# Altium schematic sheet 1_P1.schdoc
size 601 x 429 mm; Symbol: Drawing-Symbol_A2; Device: Drawing-Symbol_A2; Company: 嘉立创EDA; Version: V1.0; Page Size: A2; @Project Name: OpenSource_FlyPig v1; @Page Count: 1; @Update Date: 2025-10-14; @Create Date: 2025-10-14; @Schematic Name: Schematic1; @Page No: 1; @Page Name: P1; @Create Time: 16:01:13; @Update Time: 16:07:16; Width: 2338; Height: 1652; Region Start: 1; X Region Count: 6; Y Region Count: 4; Blade Width: 10; Title Block Position: 3; @Board Name: Board1
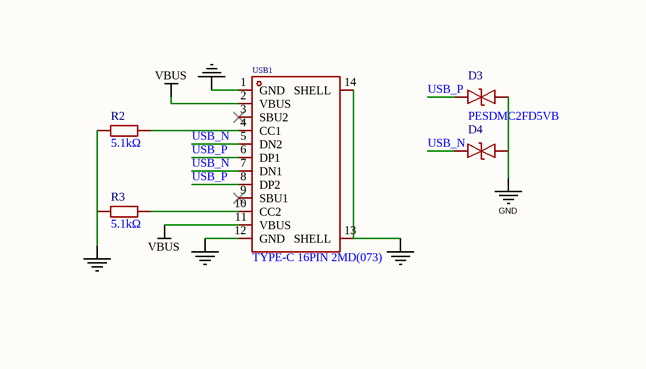
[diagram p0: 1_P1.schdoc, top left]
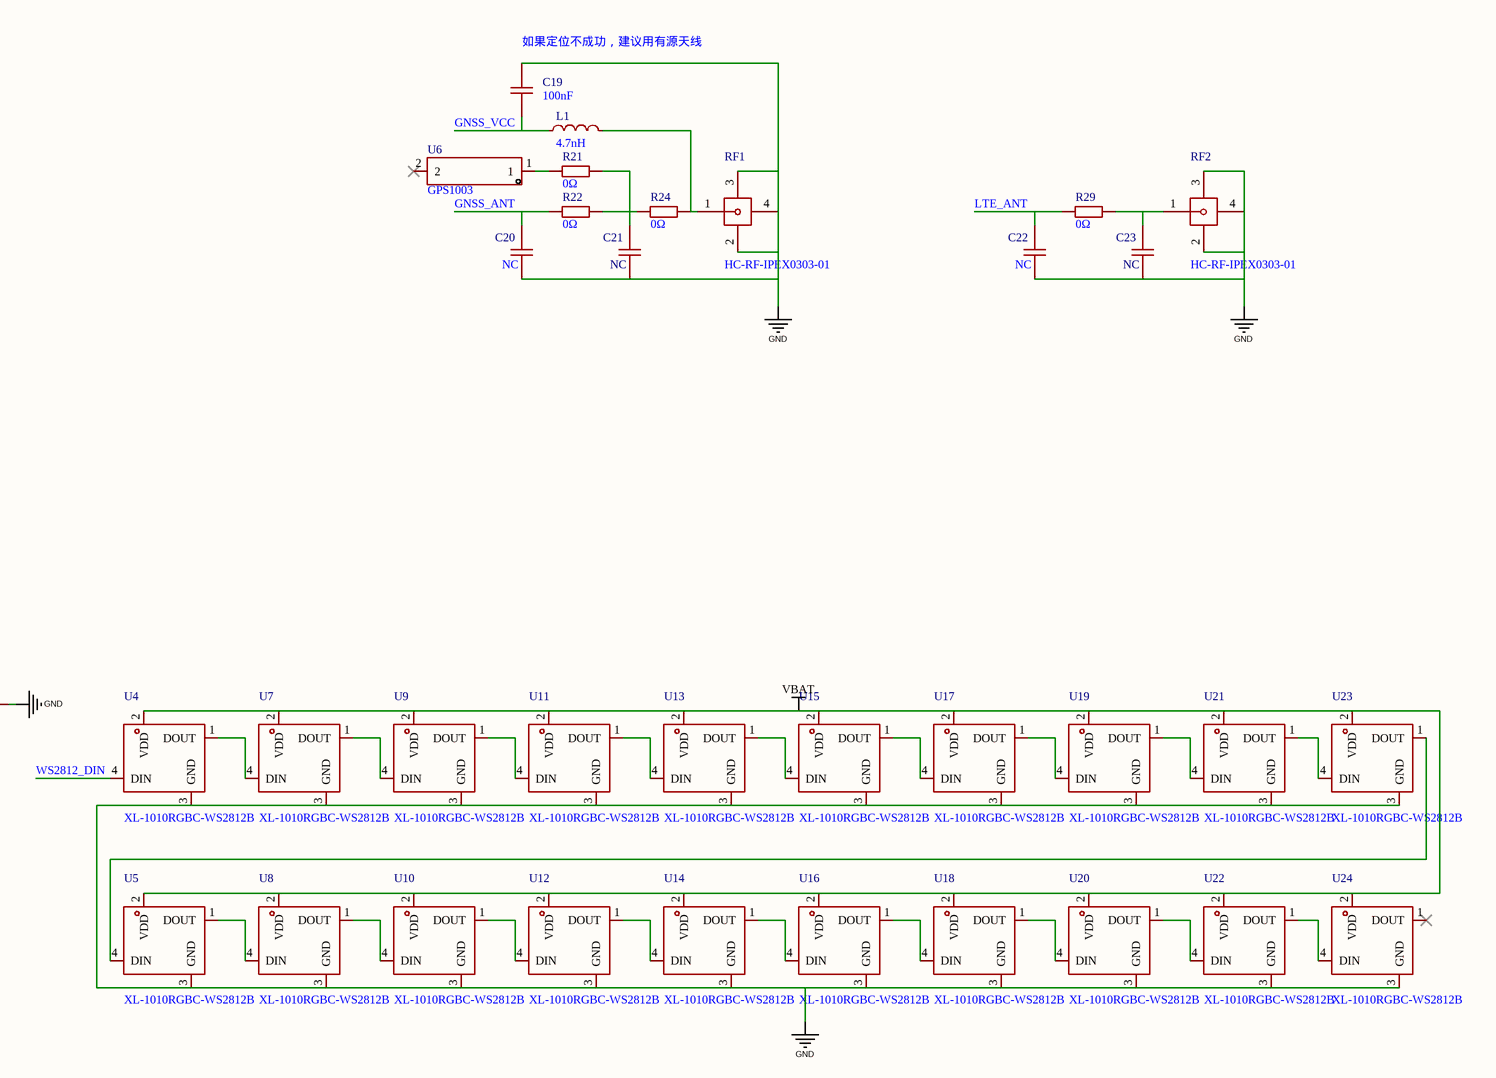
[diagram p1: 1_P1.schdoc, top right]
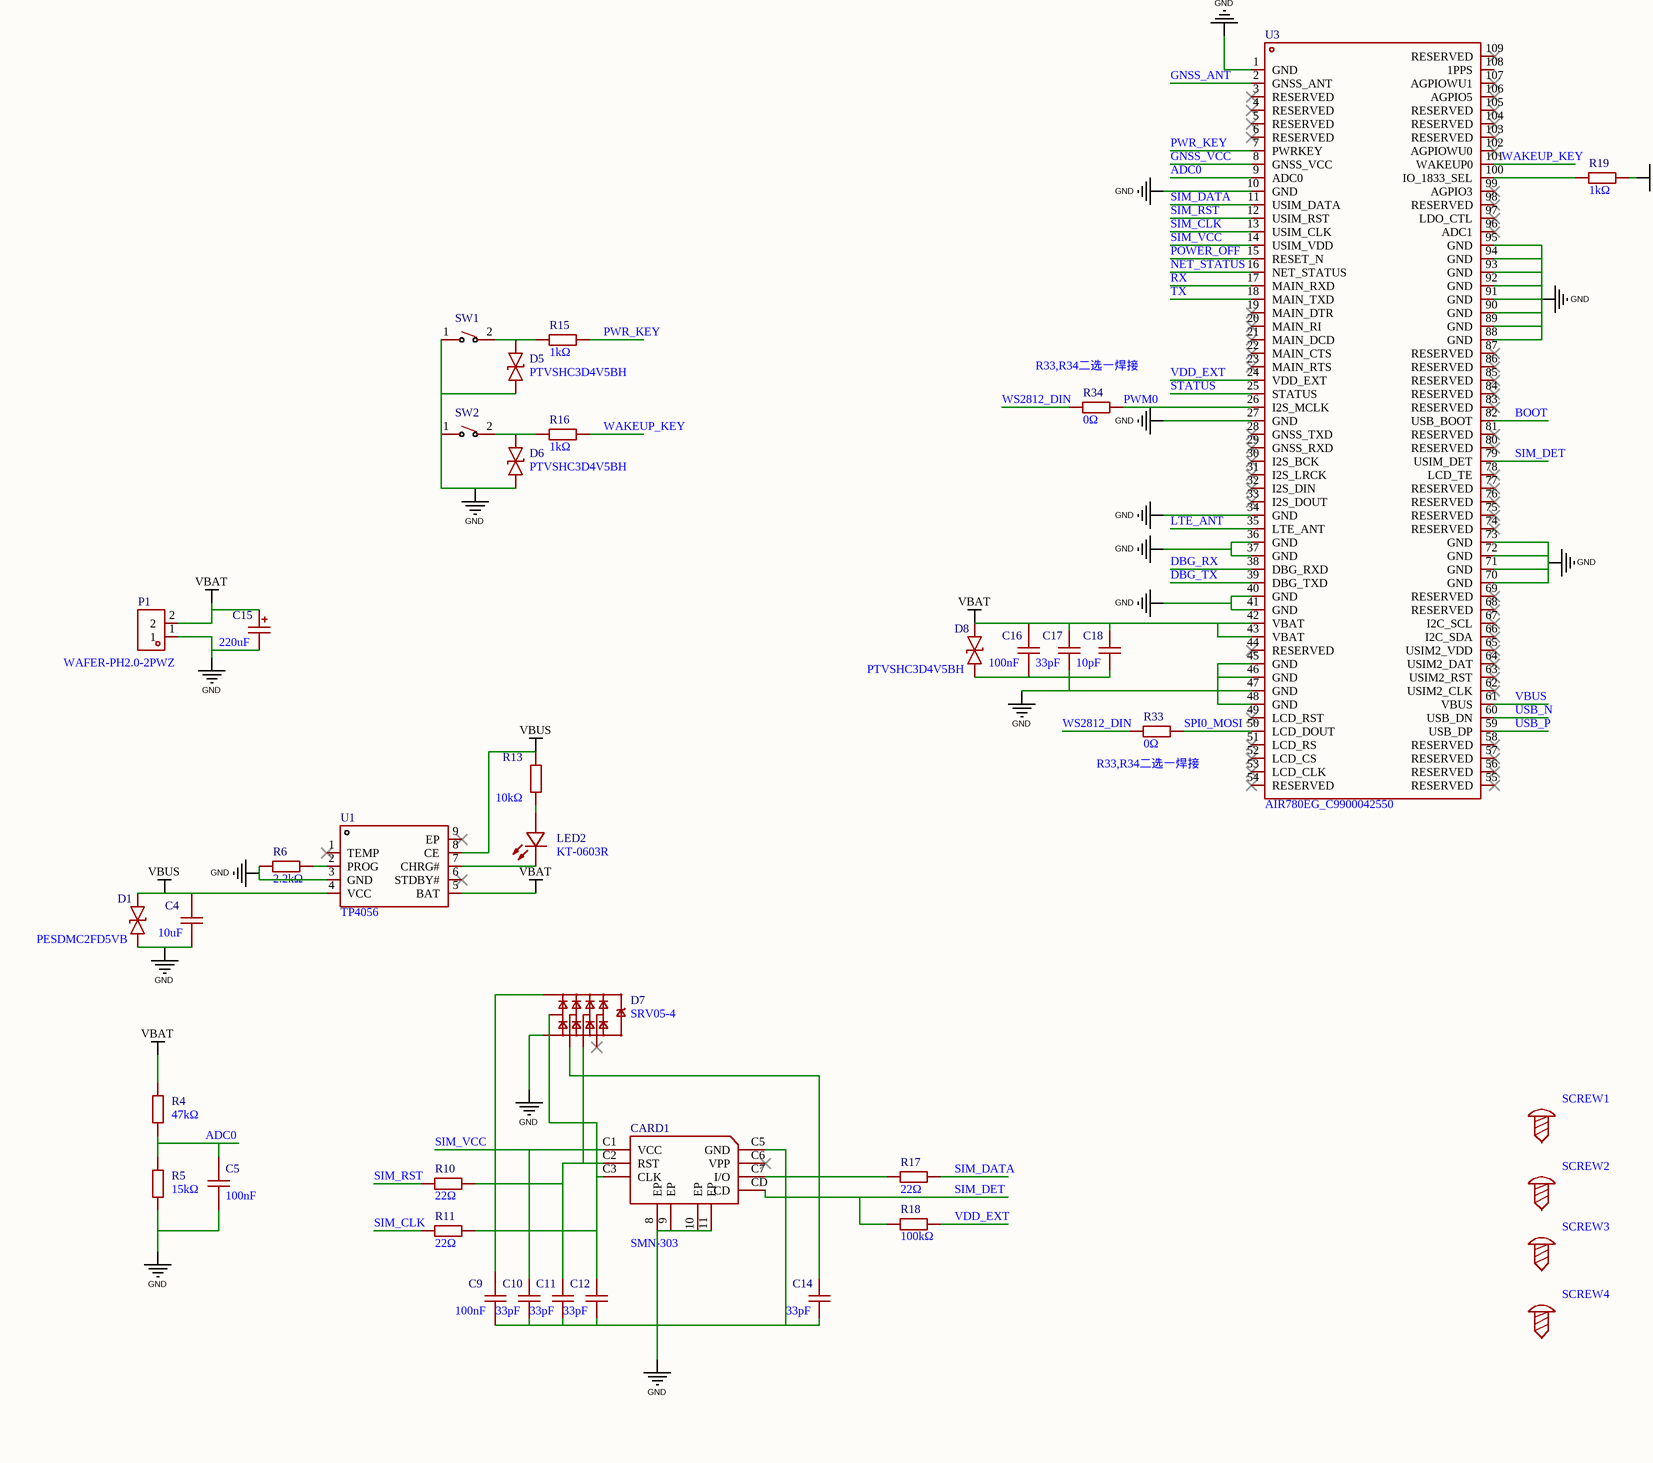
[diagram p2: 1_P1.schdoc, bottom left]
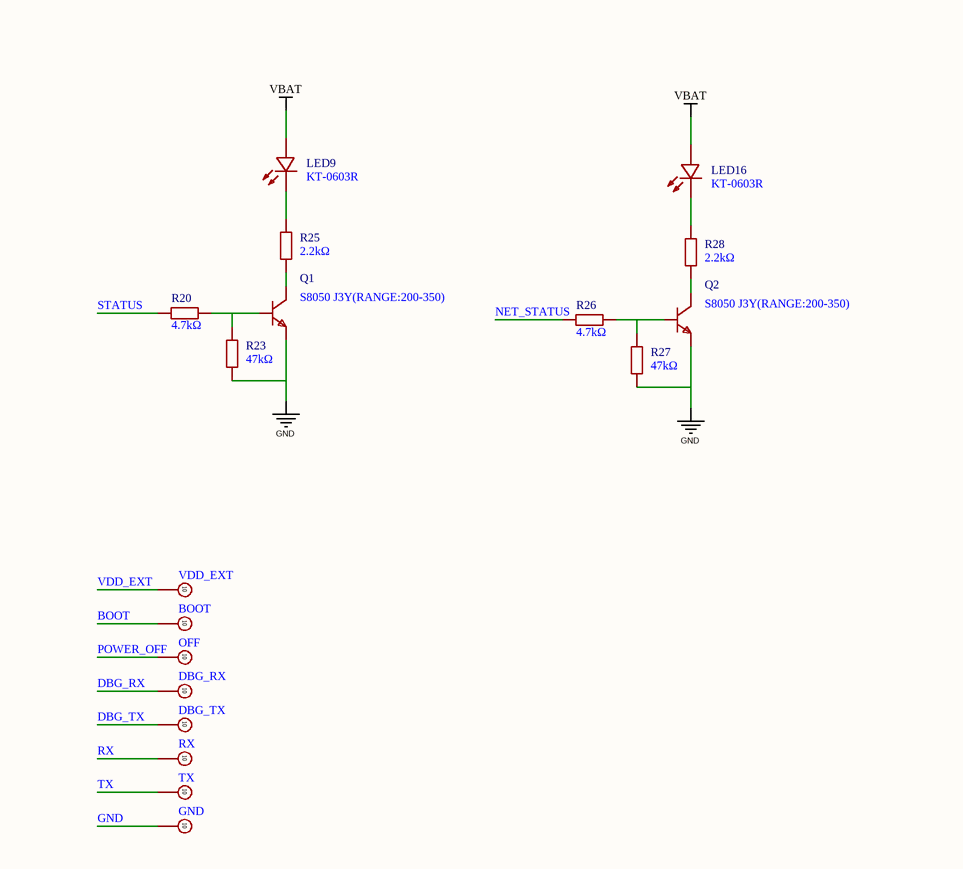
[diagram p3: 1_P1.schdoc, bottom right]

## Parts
BOOT  (no value)  [TP_10]
C4  10uF  [C0603]
C5  100nF  [C0603]
C9  100nF  [C0603]
C10  33pF  [C0603]
C11  33pF  [C0603]
C12  33pF  [C0603]
C14  33pF  [C0603]
C15  220uF  [CASE-B_3528]
C16  100nF  [C0603]
C17  33pF  [C0603]
C18  10pF  [C0603]
C19  100nF  [C0603]
C20  NC  [C0603]
C21  NC  [C0603]
C22  NC  [C0603]
C23  NC  [C0603]
CARD1  SMN-303  [SIM-SMD_SMN-303]
D1  PESDMC2FD5VB  [DFN1006-2L-BI]
D3  PESDMC2FD5VB  [DFN1006-2L-BI]
D4  PESDMC2FD5VB  [DFN1006-2L-BI]  (value not drawn)
D5  PTVSHC3D4V5BH  [SOD-323_L1.8-W1.3-LS2.5-BI]
D6  PTVSHC3D4V5BH  [SOD-323_L1.8-W1.3-LS2.5-BI]
D7  SRV05-4  [SOT-23-6_L2.9-W1.6-P0.95-LS2.8-BL-1]
D8  PTVSHC3D4V5BH  [SOD-323_L1.8-W1.3-LS2.5-BI]
DBG_RX  (no value)  [TP_10]
DBG_TX  (no value)  [TP_10]
GND  (no value)  [TP_10]
L1  4.7nH  [L0603]
LED2  KT-0603R  [LED0603-RD]
LED9  KT-0603R  [LED0603-RD]
LED16  KT-0603R  [LED0603-RD]
OFF  (no value)  [TP_10]
P1  WAFER-PH2.0-2PWZ  [CONN-TH_2P-P2.00_GP01-2001WR-2P]
Q1  S8050 J3Y(RANGE:200-350)  [SOT-23-3_L3.0-W1.7-P0.95-LS2.9-BR]
Q2  S8050 J3Y(RANGE:200-350)  [SOT-23-3_L3.0-W1.7-P0.95-LS2.9-BR]
R2  5.1kΩ  [R0603]
R3  5.1kΩ  [R0603]
R4  47kΩ  [R0603]
R5  15kΩ  [R0603]
R6  2.2kΩ  [R0603]
R10  22Ω  [R0603]
R11  22Ω  [R0603]
R13  10kΩ  [R0603]
R15  1kΩ  [R0603]
R16  1kΩ  [R0603]
R17  22Ω  [R0603]
R18  100kΩ  [R0603]
R19  1kΩ  [R0603]
R20  4.7kΩ  [R0603]
R21  0Ω  [R0603]
R22  0Ω  [R0603]
R23  47kΩ  [R0603]
R24  0Ω  [R0603]
R25  2.2kΩ  [R0603]
R26  4.7kΩ  [R0603]
R27  47kΩ  [R0603]
R28  2.2kΩ  [R0603]
R29  0Ω  [R0603]
R33  0Ω  [R0603]
R34  0Ω  [R0603]
RF1  HC-RF-IPEX0303-01  [IPEX-SMD_HC-RF-IPEX0303-01]
RF2  HC-RF-IPEX0303-01  [IPEX-SMD_HC-RF-IPEX0303-01]
RX  (no value)  [TP_10]
SCREW1  (no value)  [M3螺丝]
SCREW2  (no value)  [M3螺丝]
SCREW3  (no value)  [M3螺丝]
SCREW4  (no value)  [M3螺丝]
SW1  TSB013A4326A02  [SW-SMD_L6.0-W3.5-LS8.0]  (value not drawn)
SW2  TSB013A4326A02  [SW-SMD_L6.0-W3.5-LS8.0]  (value not drawn)
TX  (no value)  [TP_10]
U1  TP4056  [ESOP-8_L4.9-W3.9-P1.27-LS6.0-BL-EP]
U3  AIR780EG_C9900042550  [LCC-109_L17.7-W15.8-P1.10_EC800M-CN]
U4  XL-1010RGBC-WS2812B  [LED-SMD_4P-L1.0-W1.0-TL_XL-1010RGBC-WS2812B]
U5  XL-1010RGBC-WS2812B  [LED-SMD_4P-L1.0-W1.0-TL_XL-1010RGBC-WS2812B]
U6  GPS1003  [ANT-SMD_L10.0-W3.0]
U7  XL-1010RGBC-WS2812B  [LED-SMD_4P-L1.0-W1.0-TL_XL-1010RGBC-WS2812B]
U8  XL-1010RGBC-WS2812B  [LED-SMD_4P-L1.0-W1.0-TL_XL-1010RGBC-WS2812B]
U9  XL-1010RGBC-WS2812B  [LED-SMD_4P-L1.0-W1.0-TL_XL-1010RGBC-WS2812B]
U10  XL-1010RGBC-WS2812B  [LED-SMD_4P-L1.0-W1.0-TL_XL-1010RGBC-WS2812B]
U11  XL-1010RGBC-WS2812B  [LED-SMD_4P-L1.0-W1.0-TL_XL-1010RGBC-WS2812B]
U12  XL-1010RGBC-WS2812B  [LED-SMD_4P-L1.0-W1.0-TL_XL-1010RGBC-WS2812B]
U13  XL-1010RGBC-WS2812B  [LED-SMD_4P-L1.0-W1.0-TL_XL-1010RGBC-WS2812B]
U14  XL-1010RGBC-WS2812B  [LED-SMD_4P-L1.0-W1.0-TL_XL-1010RGBC-WS2812B]
U15  XL-1010RGBC-WS2812B  [LED-SMD_4P-L1.0-W1.0-TL_XL-1010RGBC-WS2812B]
U16  XL-1010RGBC-WS2812B  [LED-SMD_4P-L1.0-W1.0-TL_XL-1010RGBC-WS2812B]
U17  XL-1010RGBC-WS2812B  [LED-SMD_4P-L1.0-W1.0-TL_XL-1010RGBC-WS2812B]
U18  XL-1010RGBC-WS2812B  [LED-SMD_4P-L1.0-W1.0-TL_XL-1010RGBC-WS2812B]
U19  XL-1010RGBC-WS2812B  [LED-SMD_4P-L1.0-W1.0-TL_XL-1010RGBC-WS2812B]
U20  XL-1010RGBC-WS2812B  [LED-SMD_4P-L1.0-W1.0-TL_XL-1010RGBC-WS2812B]
U21  XL-1010RGBC-WS2812B  [LED-SMD_4P-L1.0-W1.0-TL_XL-1010RGBC-WS2812B]
U22  XL-1010RGBC-WS2812B  [LED-SMD_4P-L1.0-W1.0-TL_XL-1010RGBC-WS2812B]
U23  XL-1010RGBC-WS2812B  [LED-SMD_4P-L1.0-W1.0-TL_XL-1010RGBC-WS2812B]
U24  XL-1010RGBC-WS2812B  [LED-SMD_4P-L1.0-W1.0-TL_XL-1010RGBC-WS2812B]
USB1  TYPE-C 16PIN 2MD(073)  [USB-C-SMD_TYPE-C-6PIN-2MD-073]
VDD_EXT  (no value)  [TP_10]

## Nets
GND: C4.1 C5.1 C9.1 C10.1 C11.1 C12.1 C14.1 C15.2 C16.1 C17.1 C18.1 C19.1 C20.1 C21.1 C22.1 C23.1 CARD1.8(EP) CARD1.9(EP) CARD1.10(EP) CARD1.11(EP) CARD1.C5(GND) D1.1 D3.1 D4.1 D5.2 D6.2 D7.2 D8.1 GND.1(Pin1) P1.1 Q1.2(E) Q2.2(E) R2.1 R3.1 R5.1 R6.2 R19.1 R23.2 R27.2 RF1.2 RF1.3 RF1.4 RF2.2 RF2.3 RF2.4 SW1.1 SW2.1 U1.3(GND) U3.1(GND) U3.10(GND) U3.27(GND) U3.34(GND) U3.36(GND) U3.37(GND) U3.40(GND) U3.41(GND) U3.45(GND) U3.46(GND) U3.47(GND) U3.48(GND) U3.70(GND) U3.71(GND) U3.72(GND) U3.73(GND) U3.88(GND) U3.89(GND) U3.90(GND) U3.91(GND) U3.92(GND) U3.93(GND) U3.94(GND) U3.95(GND) U4.3(GND) U5.3(GND) U7.3(GND) U8.3(GND) U9.3(GND) U10.3(GND) U11.3(GND) U12.3(GND) U13.3(GND) U14.3(GND) U15.3(GND) U16.3(GND) U17.3(GND) U18.3(GND) U19.3(GND) U20.3(GND) U21.3(GND) U22.3(GND) U23.3(GND) U24.3(GND) USB1.1(GND) USB1.12(GND) USB1.13(SHELL) USB1.14(SHELL)
VBAT: C15.1 C16.2 C17.2 C18.2 D8.2 LED9.2(A) LED16.2(A) P1.2 R4.1 U1.5(BAT) U3.42(VBAT) U3.43(VBAT) U4.2(VDD) U5.2(VDD) U7.2(VDD) U8.2(VDD) U9.2(VDD) U10.2(VDD) U11.2(VDD) U12.2(VDD) U13.2(VDD) U14.2(VDD) U15.2(VDD) U16.2(VDD) U17.2(VDD) U18.2(VDD) U19.2(VDD) U20.2(VDD) U21.2(VDD) U22.2(VDD) U23.2(VDD) U24.2(VDD)
VBUS: C4.2 D1.2 R13.2 U1.4(VCC) U1.8(CE) U3.61(VBUS) USB1.2(VBUS) USB1.11(VBUS)
ADC0: C5.2 R4.2 R5.2 U3.9(ADC0)
BOOT: BOOT.1(Pin1) U3.82(USB_BOOT)
DBG_RX: DBG_RX.1(Pin1) U3.38(DBG_RXD)
DBG_TX: DBG_TX.1(Pin1) U3.39(DBG_TXD)
GNSS_ANT: C20.2 R22.1 U3.2(GNSS_ANT)
GNSS_VCC: C19.2 L1.1 U3.8(GNSS_VCC)
LTE_ANT: C22.2 R29.1 U3.35(LTE_ANT)
NET_STATUS: R26.1 U3.16(NET_STATUS)
POWER_OFF: OFF.1(Pin1) U3.15(RESET_N)
PWM0: R34.2 U3.26(I2S_MCLK)
PWR_KEY: R15.2 U3.7(PWRKEY)
RX: RX.1(Pin1) U3.17(MAIN_RXD)
SIM_CLK: R11.1 U3.13(USIM_CLK)
SIM_DATA: R17.1 U3.11(USIM_DATA)
SIM_DET: CARD1.CD R18.1 U3.79(USIM_DET)
SIM_RST: R10.1 U3.12(USIM_RST)
SIM_VCC: C9.2 C10.2 CARD1.C1(VCC) D7.5 U3.14(USIM_VDD)
SPI0_MOSI: R33.2 U3.50(LCD_DOUT)
STATUS: R20.1 U3.25(STATUS)
TX: TX.1(Pin1) U3.18(MAIN_TXD)
USB_N: D4.2 U3.60(USB_DN) USB1.5(DN2) USB1.7(DN1)
USB_P: D3.2 U3.59(USB_DP) USB1.6(DP1) USB1.8(DP2)
VDD_EXT: R18.2 U3.24(VDD_EXT) VDD_EXT.1(Pin1)
WAKEUP_KEY: R16.2 U3.101(WAKEUP0)
WS2812_DIN: R33.1 R34.1 U4.4(DIN)
NetC11_2: C11.2 CARD1.C2(RST) D7.4 R10.2
NetC12_2: C12.2 CARD1.C3(CLK) D7.1 R11.2
NetC14_2: C14.2 CARD1.C7(I/O) D7.3 R17.2
NetC21_2: C21.2 R21.1 R22.2 R24.1
NetC23_2: C23.2 R29.2 RF2.1
NetD5_1: D5.1 R15.1 SW1.2
NetD6_1: D6.1 R16.1 SW2.2
NetL1_2: L1.2 R24.2 RF1.1
NetLED2_1: LED2.1(K) U1.7(CHRG#)
NetLED2_2: LED2.2(A) R13.1
NetLED9_1: LED9.1(K) R25.1
NetLED16_1: LED16.1(K) R28.1
NetQ1_1: Q1.1(B) R20.2 R23.1
NetQ1_3: Q1.3(C) R25.2
NetQ2_1: Q2.1(B) R26.2 R27.1
NetQ2_3: Q2.3(C) R28.2
NetR2_2: R2.2 USB1.4(CC1)
NetR3_2: R3.2 USB1.10(CC2)
NetR6_1: R6.1 U1.2(PROG)
NetR19_2: R19.2 U3.100(IO_1833_SEL)
NetR21_2: R21.2 U6.1
NetU4_1: U4.1(DOUT) U7.4(DIN)
NetU5_1: U5.1(DOUT) U8.4(DIN)
NetU5_4: U5.4(DIN) U23.1(DOUT)
NetU7_1: U7.1(DOUT) U9.4(DIN)
NetU8_1: U8.1(DOUT) U10.4(DIN)
NetU9_1: U9.1(DOUT) U11.4(DIN)
NetU10_1: U10.1(DOUT) U12.4(DIN)
NetU11_1: U11.1(DOUT) U13.4(DIN)
NetU12_1: U12.1(DOUT) U14.4(DIN)
NetU13_1: U13.1(DOUT) U15.4(DIN)
NetU14_1: U14.1(DOUT) U16.4(DIN)
NetU15_1: U15.1(DOUT) U17.4(DIN)
NetU16_1: U16.1(DOUT) U18.4(DIN)
NetU17_1: U17.1(DOUT) U19.4(DIN)
NetU18_1: U18.1(DOUT) U20.4(DIN)
NetU19_1: U19.1(DOUT) U21.4(DIN)
NetU20_1: U20.1(DOUT) U22.4(DIN)
NetU21_1: U21.1(DOUT) U23.4(DIN)
NetU22_1: U22.1(DOUT) U24.4(DIN)

Not connected (* = marked no-connect by the designer): CARD1 C6(VPP)*; D7 6*; SCREW1 1; SCREW2 1; SCREW3 1; SCREW4 1; U1 1(TEMP)* 6(STDBY#)* 9(EP)*; U3 3(RESERVED)* 4(RESERVED)* 5(RESERVED)* 6(RESERVED)* 19(MAIN_DTR)* 20(MAIN_RI)* 21(MAIN_DCD)* 22(MAIN_CTS)* 23(MAIN_RTS)* 28(GNSS_TXD)* 29(GNSS_RXD)* 30(I2S_BCK)* 31(I2S_LRCK)* 32(I2S_DIN)* 33(I2S_DOUT)* 44(RESERVED)* 49(LCD_RST)* 51(LCD_RS)* 52(LCD_CS)* 53(LCD_CLK)* 54(RESERVED)* 55(RESERVED)* 56(RESERVED)* 57(RESERVED)* 58(RESERVED)* 62(USIM2_CLK)* 63(USIM2_RST)* 64(USIM2_DAT)* 65(USIM2_VDD)* 66(I2C_SDA)* 67(I2C_SCL)* 68(RESERVED)* 69(RESERVED)* 74(RESERVED)* 75(RESERVED)* 76(RESERVED)* 77(RESERVED)* 78(LCD_TE)* 80(RESERVED)* 81(RESERVED)* 83(RESERVED)* 84(RESERVED)* 85(RESERVED)* 86(RESERVED)* 87(RESERVED)* 96(ADC1)* 97(LDO_CTL)* 98(RESERVED)* 99(AGPIO3)* 102(AGPIOWU0)* 103(RESERVED)* 104(RESERVED)* 105(RESERVED)* 106(AGPIO5)* 107(AGPIOWU1)* 108(1PPS) 109(RESERVED)*; U6 2*; U24 1(DOUT)*; USB1 3(SBU2)* 9(SBU1)*

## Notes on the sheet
- (near C19) 如果定位不成功，建议用有源天线
- (near R34) R33,R34二选一焊接
- (near R33) R33,R34二选一焊接

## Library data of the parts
BOOT DBG_RX DBG_TX GND OFF RX TX VDD_EXT = 测试点1.0mm: Symbol: TP10; Convert to PCB: yes
C4 = CL10A106KP8NNNC: Manufacturer: SAMSUNG(三星); Add into BOM: yes; Tolerance: ±10%; Voltage Rated: 10V; Temperature Coefficient: X5R
C5 C9 C16 C19 = CC0603KRX7R9BB104: Manufacturer: YAGEO(国巨); Add into BOM: yes; Tolerance: ±10%; Voltage Rating: 50V; Temperature Coefficient: X7R
C10-C12 C14 C17 = CL10C330JB8NNNC: Manufacturer: SAMSUNG(三星); Add into BOM: yes; Tolerance: ±5%; Voltage Rated: 50V; Temperature Coefficient: C0G
C15 = TLJB227M006R0500: Manufacturer: Kyocera AVX; Add into BOM: yes; Tolerance: ±20%; Voltage Rating: 6.3V; Equivalent Series Resistance(ESR): 500mΩ@100kHz
C18 = CL10C100JB8NNNC: Manufacturer: SAMSUNG(三星); Add into BOM: yes; Tolerance: ±5%; Voltage Rated: 50V; Temperature Coefficient: C0G
C20-C23 = CC0603KRX7R9BB104: Manufacturer: YAGEO(国巨); Add into BOM: yes; Value: 100nF; Tolerance: ±10%; Voltage Rating: 50V; Temperature Coefficient: X7R
CARD1 = SMN-303: Manufacturer: XUNPU(讯普); Add into BOM: yes; Card Connection Mode: 自弹式; Card Type: NanoSIM卡; Connector Type: 卡座; Card Detection: 有插卡检测; Body Height (Max): 1.37mm
D1 D3 D4 = PESDMC2FD5VB: Manufacturer: Prisemi(芯导); Add into BOM: yes; Polarity: 双向; Reverse Stand-Off Voltage (Vrwm): 5V; Clamping Voltage: 11V; Peak Pulse Current (Ipp): 4A; Type: ESD
D5 D6 D8 = PTVSHC3D4V5BH: Manufacturer: Prisemi(芯导); Add into BOM: yes; Reverse Stand-Off Voltage (Vrwm): 5.1V; Maximum Clamping Voltage: 20V; Peak Pulse Current (Ipp): 160A@8/20us; Breakdown Voltage: 4.6V; Type: TVS
D7 = SRV05-4_C7420376: Manufacturer: 宏迦橙; Add into BOM: yes; polarity: 双向; Reverse Stand-Off Voltage (Vrwm): 5V; Maximum Clamping Voltage: 12.5V; Peak Pulse Current (Ipp): 5A; Peak Pulse Power Dissipation (Ppp): 75W; Breakdown Voltage: 6V; Reverse Leakage Current (Ir): 5uA; Number of Lines: 五路; Type: TVS
L1 = SDCL1608C4N7STDF: Manufacturer: Sunlord(顺络); Add into BOM: yes; Current Rating: 500mA; DC Resistance(DCR): 200mΩ; Q @ Frequency: 10@100MHz; Frequency - Self Resonant: 6GHz
LED2 LED9 LED16 = KT-0603R: Manufacturer: KENTO; Add into BOM: yes; Emitted Color: 红色
P1 = WAFER-PH2.0-2PWZ: Manufacturer: XUNPU(讯普); Add into BOM: yes; Pins Structure: 1x2P; Pitch: 2mm; Reference Series: PH; Number of PINs Per Row: 2; Current Rating: 2A; Voltage Rating: 250V; Plastic Material: PA66; Flame Retardant Rating: UL94V-0; Z-Height of the Board: 4.7mm; X-Length of Bottom Edge on Board (Spacing Line): 6mm; Y-Width of Bottom Edge on Board: 6.05mm
Q1 Q2 = S8050 J3Y(RANGE:200-350): Manufacturer: CJ(江苏长电/长晶); Symbol: S8050_C2146; Add into BOM: yes; type: NPN; Current - Collector(Ic): 500mA; Collector - Emitter Voltage VCEO: 25V; Pd - Power Dissipation: 300mW; DC Current Gain: 200@500mA,1V; Transition frequency(fT): 150MHz; Current - Collector Cutoff: 100nA; Vce Saturation(VCE(sat)): 600mV
R2 R3 = 0603WAF5101T5E: Manufacturer: UNI-ROYAL(厚声); Add into BOM: yes; Tolerance: ±1%; Power(Watts): 100mW; Overload Voltage (Max): 75V; Temperature Coefficient: ±100ppm/℃
R4 R23 R27 = 0603WAF4702T5E: Manufacturer: UNI-ROYAL(厚声); Add into BOM: yes; Tolerance: ±1%; Power(Watts): 100mW; Overload Voltage (Max): 75V; Temperature Coefficient: ±100ppm/℃
R5 = 0603WAF1502T5E: Manufacturer: UNI-ROYAL(厚声); Add into BOM: yes; Tolerance: ±1%; Power(Watts): 100mW; Overload Voltage (Max): 75V; Temperature Coefficient: ±100ppm/℃
R6 R25 R28 = 0603WAF2201T5E: Manufacturer: UNI-ROYAL(厚声); Add into BOM: yes; Tolerance: ±1%; Power(Watts): 100mW; Overload Voltage (Max): 75V; Temperature Coefficient: ±100ppm/℃
R10 R11 R17 = 0603WAF220JT5E: Manufacturer: UNI-ROYAL(厚声); Add into BOM: yes; Tolerance: ±1%; Power(Watts): 100mW; Overload Voltage (Max): 75V; Temperature Coefficient: ±100ppm/℃
R13 = 0603WAF1002T5E: Manufacturer: UNI-ROYAL(厚声); Add into BOM: yes; Tolerance: ±1%; Power(Watts): 100mW; Voltage-Supply(Max): 75V; Temperature Coefficient: ±100ppm/℃
R15 R16 R19 = 0603WAF1001T5E: Manufacturer: UNI-ROYAL(厚声); Add into BOM: yes; Tolerance: ±1%; Power(Watts): 100mW; Overload Voltage (Max): 75V; Temperature Coefficient: ±100ppm/℃
R18 = 0603WAF1003T5E: Manufacturer: UNI-ROYAL(厚声); Add into BOM: yes; Tolerance: ±1%; Power(Watts): 100mW; Overload Voltage (Max): 75V; Temperature Coefficient: ±100ppm/℃
R20 R26 = 0603WAF4701T5E: Manufacturer: UNI-ROYAL(厚声); Add into BOM: yes; Tolerance: ±1%; Power(Watts): 100mW; Overload Voltage (Max): 75V; Temperature Coefficient: ±100ppm/℃
R21 R22 R24 R29 R33 R34 = 0603WAF0000T5E: Manufacturer: UNI-ROYAL(厚声); Add into BOM: yes; Tolerance: ±1%; Power(Watts): 100mW; Overload Voltage (Max): 75V
RF1 RF2 = HC-RF-IPEX0303-01: Manufacturer: HCTL(华灿天禄); Add into BOM: yes; Connector Type: 板端; Interface Type: 内针; Number of Ports: 1; Interface Diameter: 2mm; Interface Length/Height: 1.25mm; RF Series: IPEX
SCREW1-SCREW4 = M3螺丝: Symbol: 螺丝孔; Convert to PCB: yes
SW1 SW2 = TSB013A4326A02: Manufacturer: BZCN(博众电气); Add into BOM: yes; Actuator Style: 矩形按钮; Operating Force: 2.6N; Switch Height: 4.3mm; Contact Current: 50mA; Voltage Rating: 12V; Actuator/Cap Color: 黑色
U1 = TP4056_C725790: Manufacturer: UMW(友台半导体); Add into BOM: yes
U3 = AIR780EG_C9900042550_C9900081146: Add into BOM: yes
U4 U5 U7-U24 = XL-1010RGBC-WS2812B: Manufacturer: XINGLIGHT(成兴光); Add into BOM: yes
U6 = GPS1003: Manufacturer: Rainsun(霖昱微); Add into BOM: yes
USB1 = TYPE-C 16PIN 2MD(073): Manufacturer: SHOU HAN(首韩); Add into BOM: yes; Gender: 母座; Number of Contacts: 16; Number of Ports: 1; Current Rating - Power (Max): 5A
